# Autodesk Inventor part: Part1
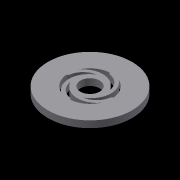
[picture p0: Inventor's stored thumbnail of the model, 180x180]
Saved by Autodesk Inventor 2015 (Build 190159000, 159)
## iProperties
Created: 2015-09
Part Number: Part1
Material: Generic
Document SubType Name: Modeling
Designer: Drano
Density: 1 g/cm^3
Appearance: Default
Author: Drano
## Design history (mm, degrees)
sketch "Sketch1"
  geometry: C1 r 25 at (-0.132, 0.627); C2 r 5.75 at (-0.132, 0.627); A1 r 12.95 centre (-0.132, 0.627) between (-1.143, 13.537) and (-11.943, 5.936); A2 r 12.95 centre (-0.132, 0.627) between (-13.042, -0.385) and (-5.442, -11.185); A3 r 12.95 centre (-0.132, 0.627) between (0.88, -12.284) and (11.68, -4.683); A4 r 12.95 centre (-0.132, 0.627) between (12.779, 1.638) and (5.178, 12.438); A5 r 8.75 centre (-0.132, 0.627) between (7.84, 4.235) and (5.917, 6.95); A6 r 8.75 centre (-0.132, 0.627) between (-3.74, 8.598) and (-6.455, 6.675); A7 r 8.75 centre (-0.132, 0.627) between (-8.103, -2.981) and (-6.18, -5.696); A8 r 8.75 centre (-0.132, 0.627) between (3.476, -7.345) and (6.191, -5.422); A9 r 11.603 centre (1.431, -1.836) between (-6.455, 6.675) and (-5.442, -11.185); A10 r 9.603 centre (1.431, -1.836) between (-8.103, -2.981) and (-0.503, -11.242); A11 r 5 centre (0.504, -6.345) between (-0.503, -11.242) and (-0.025, -11.317); A12 r 1.012 centre (-0.132, -12.323) between (0.88, -12.284) and (-0.025, -11.317); A13 r 11.603 centre (2.331, 2.19) between (-6.18, -5.696) and (11.68, -4.683); A14 r 9.603 centre (2.331, 2.19) between (3.476, -7.345) and (11.737, 0.256); A15 r 5 centre (6.84, 1.263) between (11.737, 0.256) and (11.812, 0.734); A16 r 1.012 centre (12.818, 0.627) between (12.779, 1.638) and (11.812, 0.734); A17 r 11.603 centre (-1.695, 3.09) between (6.191, -5.422) and (5.178, 12.438); A18 r 9.603 centre (-1.695, 3.09) between (7.84, 4.235) and (0.239, 12.496); A19 r 5 centre (-0.768, 7.598) between (0.239, 12.496) and (-0.239, 12.57); A20 r 1.012 centre (-0.132, 13.577) between (-1.143, 13.537) and (-0.239, 12.57); A21 r 11.603 centre (-2.595, -0.936) between (5.917, 6.95) and (-11.943, 5.936); A22 r 9.603 centre (-2.595, -0.936) between (-3.74, 8.598) and (-12.001, 0.998); A23 r 5 centre (-7.103, -0.009) between (-12.001, 0.998) and (-12.075, 0.52); A24 r 1.012 centre (-13.082, 0.627) between (-13.042, -0.385) and (-12.075, 0.52); 1 further point
  constraints: 48 point on circle, 26 centre point
extrude "Extrusion1" new body sketch "Sketch1" distance "d0" = 4; taper "d1" = 0 deg
body "Solid1"
